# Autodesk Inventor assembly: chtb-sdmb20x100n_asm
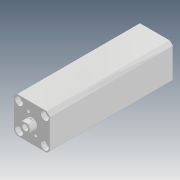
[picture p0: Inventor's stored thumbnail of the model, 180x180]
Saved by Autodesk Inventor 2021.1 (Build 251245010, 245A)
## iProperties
Company: Microsoft
Created: 2018-05
Part Number: chtb-sdmb20x100n_asm
Description: STEP AP214
Document SubType Name: Assembly
Designer: user
Title: chtb-sdmb20x100n_asm.STEP
Author: Windows
Revision Number: ÈÎºÎ
Sending System: SolidWorks 2015
Preprocessor: SwSTEP 2.0
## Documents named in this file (4)
- D:\Vault_2016\Projekty\Clamptek\Hydraulic\CHTB\CHTB-20\Inventor\CHTB-SDMB20x100N\chtb-sdmb20x100n_asm.iam
- D:\Vault_2016\Projekty\Clamptek\Hydraulic\CHTB\CHTB-20\Inventor\CHTB-SDMB20x100N\CHTB-SDMB20X100NBT.ipt
- D:\Vault_2016\Projekty\Clamptek\Hydraulic\CHTB\CHTB-20\Inventor\CHTB-SDMB20x100N\CHTB-SDMB20X100NHSG.ipt
- D:\Vault_2016\Projekty\Clamptek\Hydraulic\CHTB\CHTB-20\Inventor\CHTB-SDMB20x100N\QG_3.ipt
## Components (3 placed, 3 different names)
1. CHTB-SDMB20X100NBT_1
2. CHTB-SDMB20X100NHSG_2
3. QG_3_3
